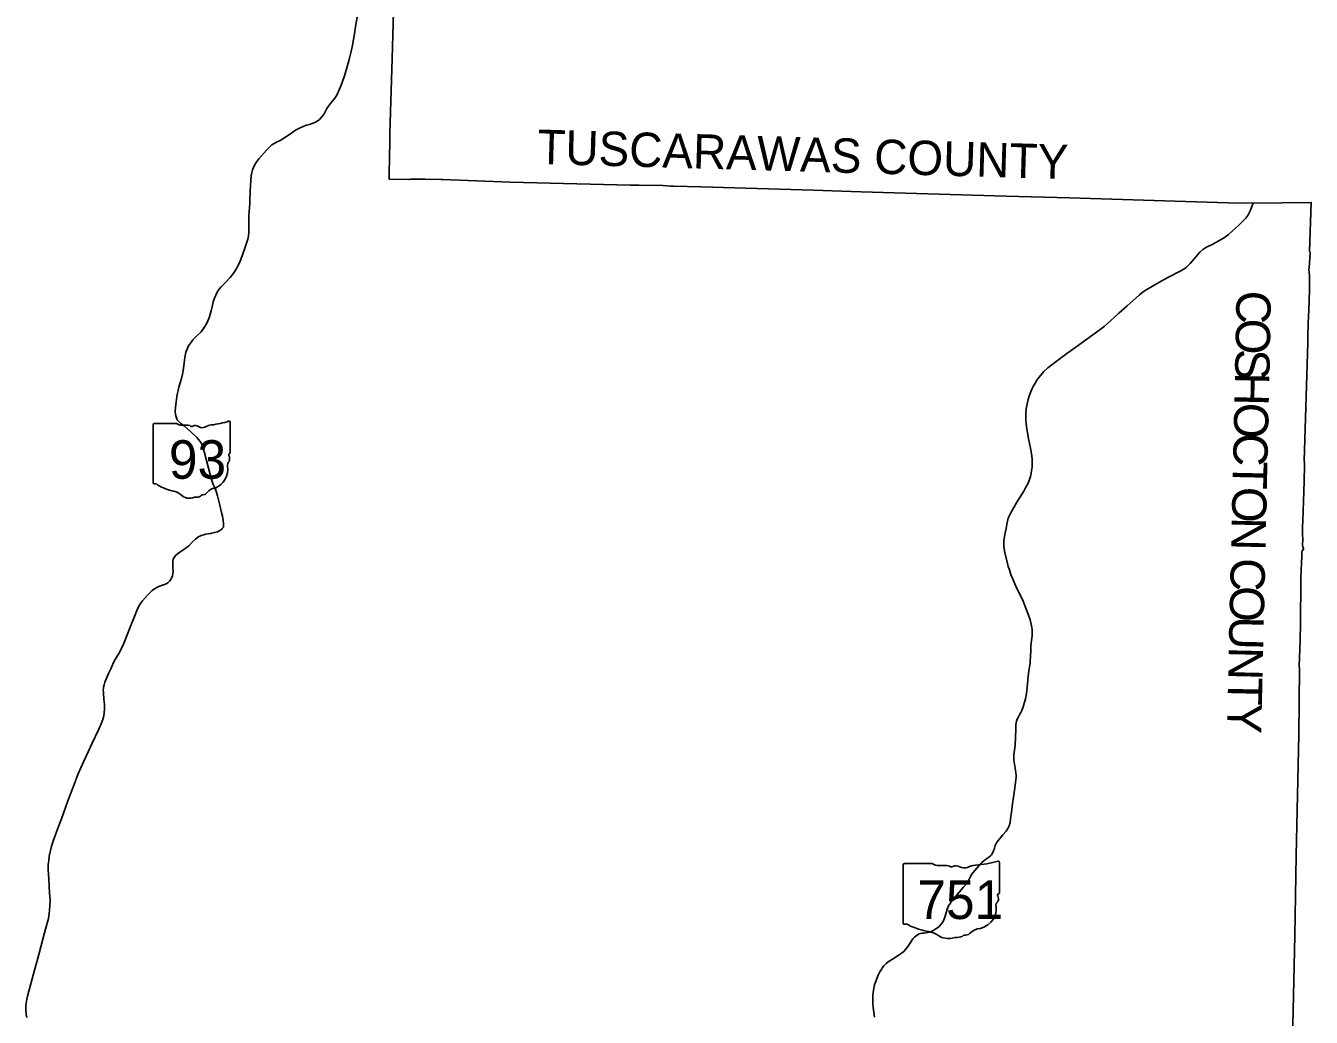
# Model space of a CAD drawing. Extents: x 1913970 to 2276415, y 78841 to 927181.
# Drawn here: x 2177346 to 2214759, y 840084 to 868928 of the extents above; entities that cross this region are included whole.
import ezdxf

# ---------------------------------------------------------------- set-up
doc = ezdxf.new("R2010")
doc.units = 0
for name, color, linetype in [('GM_X_County', 7, 'Continuous'), ('GM_X_County_Text', 7, 'Continuous'), ('GM_X_State_Location', 7, 'Continuous'), ('GM_X_State_Route', 7, 'Continuous'), ('GM_X_State_Shield', 7, 'Continuous')]:
    doc.layers.add(name, color=color, linetype=linetype)

msp = doc.modelspace()

# ---------------------------------------------------------------- linework, layer by layer
at = {"layer": 'GM_X_County'}
msp.add_lwpolyline([(2188107, 871377), (2188009, 867975), (2187946, 865793), (2187943, 865563), (2187924, 864631), (2187921, 864465), (2188480, 864451), (2188549, 864467), (2188971, 864466), (2189427, 864451), (2189489, 864451), (2191444, 864380), (2194934, 864291), (2195070, 864290), (2195195, 864289), (2195884, 864276), (2196109, 864261), (2196154, 864260), (2196195, 864259), (2196999, 864238), (2200266, 864143), (2201652, 864100), (2205881, 863975), (2207719, 863920), (2212337, 863781), (2213068, 863770), (2214759, 863787), (2214712, 862361), (2214713, 862356), (2214726, 862318), (2214720, 862172), (2214712, 862011), (2214697, 861892), (2214689, 861834), (2214694, 861764), (2214704, 861652), (2214711, 861298), (2214695, 860899), (2214692, 860688), (2214680, 860444), (2214670, 860308), (2214664, 860127), (2214654, 860032), (2214655, 859699), (2214553, 856272), (2214557, 856218), (2214550, 855598), (2214546, 855462), (2214541, 855352), (2214528, 855120), (2214520, 854788), (2214518, 854552), (2214507, 854329), (2214505, 854132), (2214511, 853994), (2214501, 853822), (2214513, 853771), (2214537, 853723), (2214530, 853697), (2214491, 853649), (2214483, 853607), (2214483, 853542), (2214483, 853506), (2214474, 853287), (2214468, 853109), (2214458, 852828), (2214455, 852617), (2214452, 852373), (2214451, 852227), (2214446, 852103), (2214442, 851561), (2214438, 851040), (2214411, 850311), (2214412, 850218), (2214393, 848301), (2214324, 844793), (2214279, 842459), (2214173, 837662)], dxfattribs=at)
at = {"layer": 'GM_X_State_Route'}
for points in [[(2183864, 863756), (2183871, 863833), (2183883, 864126), (2183887, 864262), (2183894, 864435), (2183908, 864562), (2183925, 864659), (2183945, 864734), (2183972, 864808), (2184007, 864870), (2184055, 864947), (2184134, 865056), (2184349, 865304), (2184449, 865409), (2184513, 865461), (2184573, 865499), (2184662, 865547), (2184755, 865591), (2184832, 865635), (2184933, 865704), (2185086, 865812), (2185202, 865886), (2185332, 865958), (2185417, 865998), (2185507, 866033), (2185608, 866058), (2185713, 866092), (2185800, 866131), (2185894, 866199), (2185959, 866270), (2186018, 866346), (2186062, 866424), (2186114, 866525), (2186155, 866590), (2186213, 866662), (2186342, 866821), (2186405, 866913), (2186472, 867060), (2186526, 867197), (2186612, 867437), (2186678, 867665), (2186755, 867949), (2186815, 868182), (2186860, 868364), (2186916, 868694), (2186948, 868905), (2187000, 869228)], [(2183067, 854300), (2183098, 854341), (2183103, 854383), (2183101, 854453), (2183090, 854535), (2183069, 854663), (2183044, 854772), (2182991, 854982), (2182931, 855250), (2182886, 855386), (2182848, 855481), (2182802, 855583), (2182757, 855733), (2182669, 856056), (2182609, 856277), (2182549, 856505), (2182505, 856671), (2182473, 856755), (2182420, 856838), (2182323, 856950), (2182156, 857116), (2182058, 857204), (2181965, 857282), (2181865, 857359), (2181801, 857418), (2181758, 857468), (2181726, 857547), (2181708, 857623), (2181698, 857715), (2181702, 857820), (2181724, 857991), (2181744, 858129), (2181757, 858205), (2181779, 858314), (2181805, 858410), (2181883, 858664), (2181912, 858795), (2181935, 858956), (2181955, 859118), (2181978, 859278), (2182010, 859428), (2182043, 859521), (2182088, 859613), (2182139, 859698), (2182211, 859787), (2182330, 859903), (2182448, 860027), (2182543, 860150), (2182605, 860259), (2182683, 860434), (2182743, 860635), (2182782, 860799), (2182805, 860896), (2182837, 861000), (2182875, 861095), (2182905, 861161), (2182968, 861252), (2183039, 861336), (2183160, 861458), (2183300, 861607), (2183401, 861739), (2183466, 861847), (2183521, 861939), (2183573, 862052), (2183654, 862259), (2183725, 862457), (2183811, 862718), (2183833, 862816), (2183842, 862901), (2183843, 862989), (2183839, 863139), (2183841, 863250), (2183844, 863411), (2183847, 863527), (2183864, 863756)], [(2202046, 840083), (2202010, 840372), (2201999, 840489), (2201998, 840608), (2202001, 840714), (2202012, 840810), (2202029, 840931), (2202051, 841024), (2202078, 841110), (2202158, 841311), (2202215, 841427), (2202247, 841478), (2202284, 841534), (2202322, 841584), (2202389, 841652), (2202448, 841702), (2202492, 841731), (2202646, 841823), (2202809, 841927), (2202866, 841971), (2202901, 842000), (2202952, 842052), (2203024, 842154), (2203164, 842362), (2203212, 842416), (2203259, 842457), (2203297, 842483), (2203351, 842509), (2203429, 842529), (2203486, 842531), (2203546, 842537), (2203605, 842546), (2203664, 842565), (2203756, 842604), (2203883, 842685), (2203934, 842728), (2203970, 842771), (2204020, 842834), (2204054, 842888), (2204098, 842996), (2204130, 843119), (2204161, 843225), (2204204, 843323), (2204246, 843395), (2204296, 843467), (2204410, 843603), (2204632, 843855), (2204718, 843956), (2204748, 843997), (2204781, 844049), (2204806, 844105), (2204842, 844183), (2204884, 844251), (2204968, 844353), (2205086, 844491), (2205166, 844579), (2205225, 844633), (2205281, 844676), (2205368, 844734), (2205421, 844778), (2205454, 844812), (2205483, 844858), (2205511, 844925), (2205538, 845002), (2205563, 845079), (2205600, 845156), (2205650, 845230), (2205711, 845306), (2205783, 845389), (2205880, 845499), (2205932, 845573), (2205967, 845652), (2205994, 845753), (2206007, 845856), (2206041, 846115), (2206055, 846228), (2206099, 846554), (2206119, 846694), (2206151, 846900), (2206164, 846992), (2206171, 847070), (2206170, 847126), (2206163, 847200), (2206149, 847277), (2206114, 847502), (2206107, 847565), (2206102, 847646), (2206107, 847730), (2206121, 847850), (2206137, 848003), (2206147, 848226), (2206156, 848464), (2206159, 848508), (2206165, 848599), (2206172, 848648), (2206185, 848694), (2206204, 848757), (2206234, 848820), (2206278, 848902), (2206303, 848949), (2206332, 849010), (2206374, 849113), (2206397, 849186), (2206438, 849345), (2206469, 849504), (2206482, 849603), (2206501, 849789), (2206521, 850010), (2206540, 850154), (2206576, 850392), (2206582, 850454), (2206588, 850562), (2206596, 850786), (2206601, 850901), (2206638, 851181), (2206641, 851284), (2206638, 851362), (2206630, 851427), (2206611, 851519), (2206576, 851643), (2206531, 851779), (2206435, 852036), (2206371, 852187), (2206313, 852311), (2206204, 852540), (2206129, 852698), (2206073, 852827), (2206020, 852968), (2205973, 853102), (2205941, 853198), (2205916, 853288), (2205844, 853606), (2205824, 853714), (2205810, 853802), (2205810, 853882), (2205814, 853943), (2205822, 854014), (2205845, 854131), (2205878, 854307), (2205908, 854482), (2205924, 854556), (2205939, 854604), (2205964, 854659), (2206018, 854761), (2206194, 855069), (2206391, 855391), (2206455, 855504), (2206507, 855606), (2206547, 855703), (2206583, 855814), (2206606, 855902), (2206620, 855986), (2206634, 856086), (2206639, 856188), (2206634, 856309), (2206623, 856414), (2206587, 856635), (2206534, 856911), (2206511, 857035), (2206482, 857196), (2206460, 857359), (2206452, 857450), (2206449, 857556), (2206451, 857641), (2206462, 857783), (2206480, 857880), (2206496, 857967), (2206519, 858052), (2206549, 858153), (2206589, 858259), (2206631, 858357), (2206667, 858431), (2206722, 858529), (2206775, 858614), (2206835, 858697), (2206886, 858761), (2206976, 858869), (2207094, 858978), (2207166, 859039), (2207374, 859193), (2207647, 859390), (2207975, 859630), (2208155, 859761), (2208471, 859985), (2208729, 860181), (2208916, 860341), (2209158, 860562), (2209401, 860779), (2209663, 861016), (2209758, 861100), (2209842, 861164), (2209975, 861253), (2210323, 861460), (2210587, 861602), (2210965, 861794), (2211054, 861849), (2211115, 861900), (2211236, 862015), (2211353, 862143), (2211518, 862337), (2211602, 862422), (2211657, 862458), (2211728, 862500), (2211871, 862569), (2211978, 862623), (2212114, 862698), (2212204, 862751), (2212336, 862846), (2212471, 862959), (2212642, 863116), (2212757, 863229), (2212856, 863331), (2212911, 863412), (2212978, 863540), (2213069, 863767)], [(2179609, 849649), (2179614, 849692), (2179626, 849755), (2179651, 849835), (2179704, 849966), (2179764, 850101), (2179831, 850242), (2179873, 850336), (2179881, 850354), (2179919, 850439), (2179980, 850540), (2180055, 850667), (2180159, 850870), (2180213, 850982), (2180298, 851212), (2180401, 851481), (2180508, 851746), (2180584, 851922), (2180643, 852044), (2180687, 852122), (2180742, 852200), (2180893, 852365), (2180978, 852454), (2181029, 852501), (2181096, 852550), (2181158, 852586), (2181236, 852623), (2181381, 852674), (2181434, 852698), (2181485, 852727), (2181532, 852768), (2181570, 852820), (2181591, 852854), (2181616, 852928), (2181631, 852991), (2181636, 853063), (2181630, 853163), (2181626, 853267), (2181627, 853345), (2181642, 853408), (2181666, 853464), (2181708, 853516), (2181758, 853560), (2181831, 853617), (2181917, 853676), (2182012, 853740), (2182090, 853803), (2182188, 853901), (2182292, 853996), (2182360, 854048), (2182454, 854096), (2182526, 854120), (2182582, 854135), (2182734, 854160)], [(2182734, 854160), (2182749, 854163), (2182845, 854184), (2182928, 854210), (2182999, 854245), (2183058, 854288), (2183067, 854300)], [(2177376, 840079), (2177359, 840166), (2177346, 840308), (2177350, 840407), (2177358, 840496), (2177377, 840610), (2177407, 840742), (2177592, 841418), (2177724, 841906), (2177896, 842537), (2177973, 842823), (2178006, 842959), (2178029, 843092), (2178043, 843203), (2178052, 843331), (2178055, 843489), (2178042, 843699), (2178015, 844116), (2178003, 844378), (2178004, 844525), (2178015, 844644), (2178032, 844770), (2178064, 844932), (2178099, 845061), (2178157, 845234), (2178276, 845559), (2178387, 845860), (2178576, 846378), (2178752, 846853), (2178866, 847148), (2178950, 847343), (2179035, 847534), (2179160, 847804), (2179268, 848034), (2179476, 848463), (2179546, 848625), (2179588, 848742), (2179608, 848815), (2179628, 848918), (2179637, 849069), (2179636, 849184), (2179621, 849342), (2179606, 849525), (2179605, 849612), (2179609, 849649)]]:
    msp.add_lwpolyline(points, dxfattribs=at)
at = {"layer": 'GM_X_State_Shield'}
for p, q in [((2181056, 857331), (2181056, 855630)), ((2181735, 857361), (2181078, 857361)), ((2183298, 856513), (2183298, 857403)), ((2183297, 856513), (2183298, 856513)), ((2202880, 844524), (2202880, 842823)), ((2203728, 844553), (2202907, 844553)), ((2205681, 843705), (2205681, 844595)), ((2205681, 843706), (2205681, 843705))]:
    msp.add_line(p, q, dxfattribs=at)
for centre, radius, start, end in [((2181082, 857335), 26, 98.1301, 188.1301), ((2181891, 857558), 252, 231.6195, 271.1119), ((2181975, 856406), 904, 80.4867, 94.9883), ((2182180, 857344), 72.7, 219.7921, 297.1024), ((2182287, 857147), 151, 54.4667, 119.1411), ((2182482, 857417), 182, 233.8562, 294.8282), ((2182802, 856841), 478, 97.3462, 120.7689), ((2182499, 859680), 2377, 275.8445, 288.9065), ((2183273, 857406), 25, 351.8621, 97.738), ((2183292, 856448), 38.6, 107.944, 210.337), ((2183046, 856335), 232, 340.033, 23.6496), ((2183271, 856509), 26.7, 289.6038, 7.7341), ((2182632, 856027), 595, 292.3089, 8.9858), ((2183387, 856140), 169, 136.8065, 186.9296), ((2181082, 855626), 26.2, 171.9584, 258.3066), ((2181086, 855800), 200, 267.339, 280.6039), ((2181127, 855532), 72.1, 29.7484, 93.2717), ((2182037, 857060), 1716, 240.4129, 257.1985), ((2181525, 854866), 537, 47.1842, 75.836), ((2182328, 855396), 182, 268.777, 315.5493), ((2182492, 855231), 51.1, 65.7517, 132.6484), ((2182471, 855465), 192, 282.8732, 323.2771), ((2182883, 855153), 326, 94.4031, 142.5768), ((2182106, 855524), 341, 230.7004, 286.2918), ((2182303, 854935), 280, 85.6951, 111.2099)]:
    msp.add_arc(centre, radius, start, end, dxfattribs=at)
for centre, major_axis, start_param, end_param in [((2202912, 844527), (32.5, 0), 1.712693, 3.28349), ((2203923, 844751), (315, 0), 4.042523, 4.731795), ((2204028, 843598), (1130, 0), 1.404758, 1.657858), ((2204284, 844536), (90.8, 0), 3.836095, 5.185415), ((2204417, 844340), (189, 0), 0.950623, 2.079405), ((2204661, 844609), (227, 0), 4.081561, 5.145723), ((2205062, 844034), (598, 0), 1.699011, 2.107814), ((2204683, 846872), (2971, 0), 4.814394, 5.042369), ((2205650, 844599), (31.2, 0), 6.141152, 7.989035), ((2205674, 843640), (48.3, 0), 1.883978, 3.671073), ((2205648, 843702), (33.4, 0), 5.05454, 6.418171), ((2204850, 843220), (743, 0), 5.101752, 6.440018), ((2205793, 843333), (211, 0), 2.387724, 3.262537), ((2205367, 843528), (290, 0), 5.934695, 6.695948), ((2202912, 842819), (32.7, 0), 3.00124, 4.508301), ((2202917, 842993), (250, 0), 4.665946, 4.897461), ((2202968, 842725), (90.1, 0), 0.519207, 1.627899), ((2204106, 844253), (2146, 0), 4.195997, 4.488961), ((2203466, 842058), (671, 0), 0.823519, 1.323587), ((2205163, 842345), (407, 0), 1.647645, 2.488434), ((2204192, 842716), (426, 0), 4.026481, 4.996735), ((2204438, 842128), (350, 0), 1.495662, 1.94098), ((2204469, 842589), (227, 0), 4.691044, 5.507374), ((2204675, 842424), (63.9, 0), 1.147584, 2.315152), ((2204648, 842658), (240, 0), 4.937069, 5.64225)]:
    msp.add_ellipse(centre, major_axis=major_axis, ratio=0.8, start_param=start_param, end_param=end_param, dxfattribs=at)

# ---------------------------------------------------------------- texts
at = {"layer": 'GM_X_County_Text'}
for s, rotation, p in [('TUSCARAWAS COUNTY', 358.3405, (2192224, 864911)), ('C', 269.2627, (2212581, 861226)), ('O', 268.9973, (2212570, 860414)), ('S', 268.856, (2212555, 859530)), ('H', 268.7559, (2212541, 858853)), ('O', 268.7124, (2212522, 857969)), ('C', 268.6908, (2212502, 857085)), ('T', 268.6961, (2212484, 856271)), ('O', 268.6928, (2212467, 855523)), ('N', 268.6954, (2212447, 854639)), ('C', 268.6964, (2212419, 853451)), ('O', 268.6928, (2212401, 852637)), ('U', 268.6954, (2212381, 851753)), ('N', 268.6928, (2212361, 850869)), ('T', 268.695, (2212340, 849985)), ('Y', 268.6954, (2212323, 849237))]:
    msp.add_text(s, height=1000, rotation=rotation, dxfattribs=at).set_placement(p)
at = {"layer": 'GM_X_State_Location'}
for s, p in [('93', (2182334, 856687)), ('751', (2204206, 843426))]:
    msp.add_text(s, height=1, rotation=0, dxfattribs=at).set_placement(p)
for s, p in [('s', (2182586, 856760)), ('r', (2182586, 856760)), ('s', (2204559, 843498)), ('r', (2204559, 843498))]:
    msp.add_text(s, height=1, dxfattribs=at).set_placement(p)
at = {"layer": 'GM_X_State_Shield'}
for s, p in [('93', (2181512, 855750)), ('751', (2203293, 842943))]:
    msp.add_text(s, height=1120.7, dxfattribs=at).set_placement(p)

doc.saveas('drawing.dxf')
